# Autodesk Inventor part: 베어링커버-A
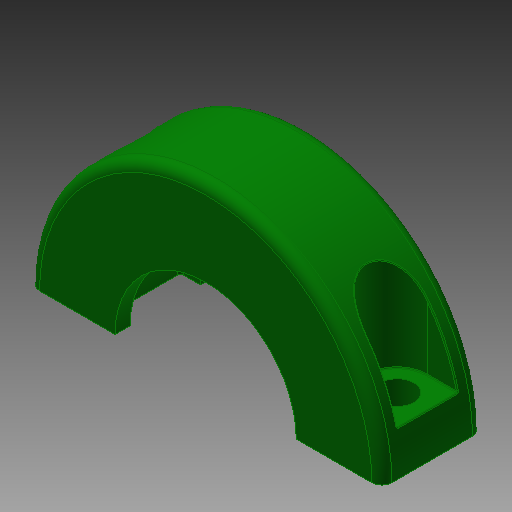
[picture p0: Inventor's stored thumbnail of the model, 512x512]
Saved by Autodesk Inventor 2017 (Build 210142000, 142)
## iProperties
Created: 2018-01
Part Number: 베어링커버-A
Material: 알루미늄 6061
Document SubType Name: Modeling
Designer: mduedu
Density: 2.71 g/cm^3
Mass: 7.15169 g
Surface Area: 19.8517 cm^2
Volume: 2.639 cm^3
Appearance: 진녹색
Author: mduedu
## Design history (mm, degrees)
sketch "스케치1"
  geometry: L1 (-17.5, 0)-(17.5, 0); A1 r 17.5 centre (0, 0) between (-17.5, 0) and (17.5, 0); 2 further points
  constraints: 2 coincident, 2 end point, 2 point on circle, 1 centre point, 1 horizontal, 1 midpoint
  dimensions: "d0" = 35 diameter of A1
extrude "돌출1" new body sketch "스케치1" stored distance "d1" = 10; taper "d2" = 0 deg
sketch "스케치2"
  geometry: C1 r 11 at (0, 0); C2 r 9 at (0, 0); 1 further point
  constraints: 2 centre point, 2 coincident
  dimensions: "d3" = 22 diameter of C1; "d4" = 18 diameter of C2
extrude "돌출2" cut sketch "스케치2" stored distance "d5" = 7; taper "d6" = 0 deg
extrude "돌출3" cut sketch "스케치2" stored distance "d7" = 7; taper "d8" = 0 deg
fillet "모깎기1" dims "d9" = 0.3
fillet "모깎기2" dims "d10" = 1
node "작업 평면1"
sketch "스케치3"
  geometry: L1 (-15.5, -3.5)-(33.5, -3.5) reference; L2 (-5, -6.5)-(-8.037, -6.5); L3 (-8.037, -6.5)-(-8.037, -0.5); L4 (-8.037, -0.5)-(-5, -0.5); L5 (-0.924, -7)-(0.938, -7) reference; L6 (0.938, -7)-(0.938, -8.5) reference; L7 (0.938, -8.5)-(-7.008, -8.5) reference; L8 (-8.037, -7.5)-(-8.037, 0.5) reference; L9 (-7.008, 1.5)-(0.938, 1.5) reference; L10 (0.938, 1.5)-(0.938, 0) reference; L11 (0.938, 0)-(-0.924, 0) reference; L12 (-1.247, -0.3)-(-1.247, -6.7) reference; L13 (19.247, -6.7)-(19.247, -0.3) reference; L14 (18.924, 0)-(17.062, 0) reference; L15 (17.062, 0)-(17.062, 1.5) reference; L16 (17.062, 1.5)-(25.008, 1.5) reference; L17 (26.037, 0.5)-(26.037, -7.5) reference; L18 (25.008, -8.5)-(17.062, -8.5) reference; L19 (17.062, -8.5)-(17.062, -7) reference; L20 (17.062, -7)-(18.924, -7) reference; A1 r 3 centre (-5, -3.5) between (-5, -6.5) and (-5, -0.5); 1 further point
  constraints: 6 end point, 2 point on circle, 2 tangent, 1 centre point, 1 collinear, 1 horizontal, 1 parallel, 1 perpendicular, 1 point on line, 8 other
  dimensions: "d12" = 6 distance between parallel lines of L4 L2; "d28" = 14 distance of point (9, -3.5) A1.centre
extrude "돌출4" cut sketch "스케치3" stored distance "d15" = 0; taper "d16" = 0 deg
sketch "스케치4"
  geometry: 7 further points
  constraints: 4 vertical alignment, 2 horizontal alignment
sketch "스케치5"
  geometry: L1 (-26.5, -0.5)-(-26.5, 7.5) reference; L2 (-18, 8.5)-(-25.5, 8.5) reference; 2 further points
  constraints: 1 horizontal alignment
  dimensions: "d25" = 3.5 distance from line of point (-23, 3.5) L1; "d26" = 28 distance of point (5, 3.5) point (-23, 3.5); "d27" = 5 distance from line of L2 point (-23, 3.5)
hole "구멍1" sketch "스케치5" at (-23, 3.5), (5, 3.5) diameter "d17" = 3.4; stored, may be unused: countersink angle "d21" = 90 deg, drill point angle "d23" = 0 deg; dims "d18" = 6, "d19" = 4, "d20" = 2, "d22" = 8
fillet "모깎기3" dims "d24" = 0.1
node "솔리드1"
mirror "대칭1"
node "절단 모서리 투영1"
other parameters: "d11" = -4
